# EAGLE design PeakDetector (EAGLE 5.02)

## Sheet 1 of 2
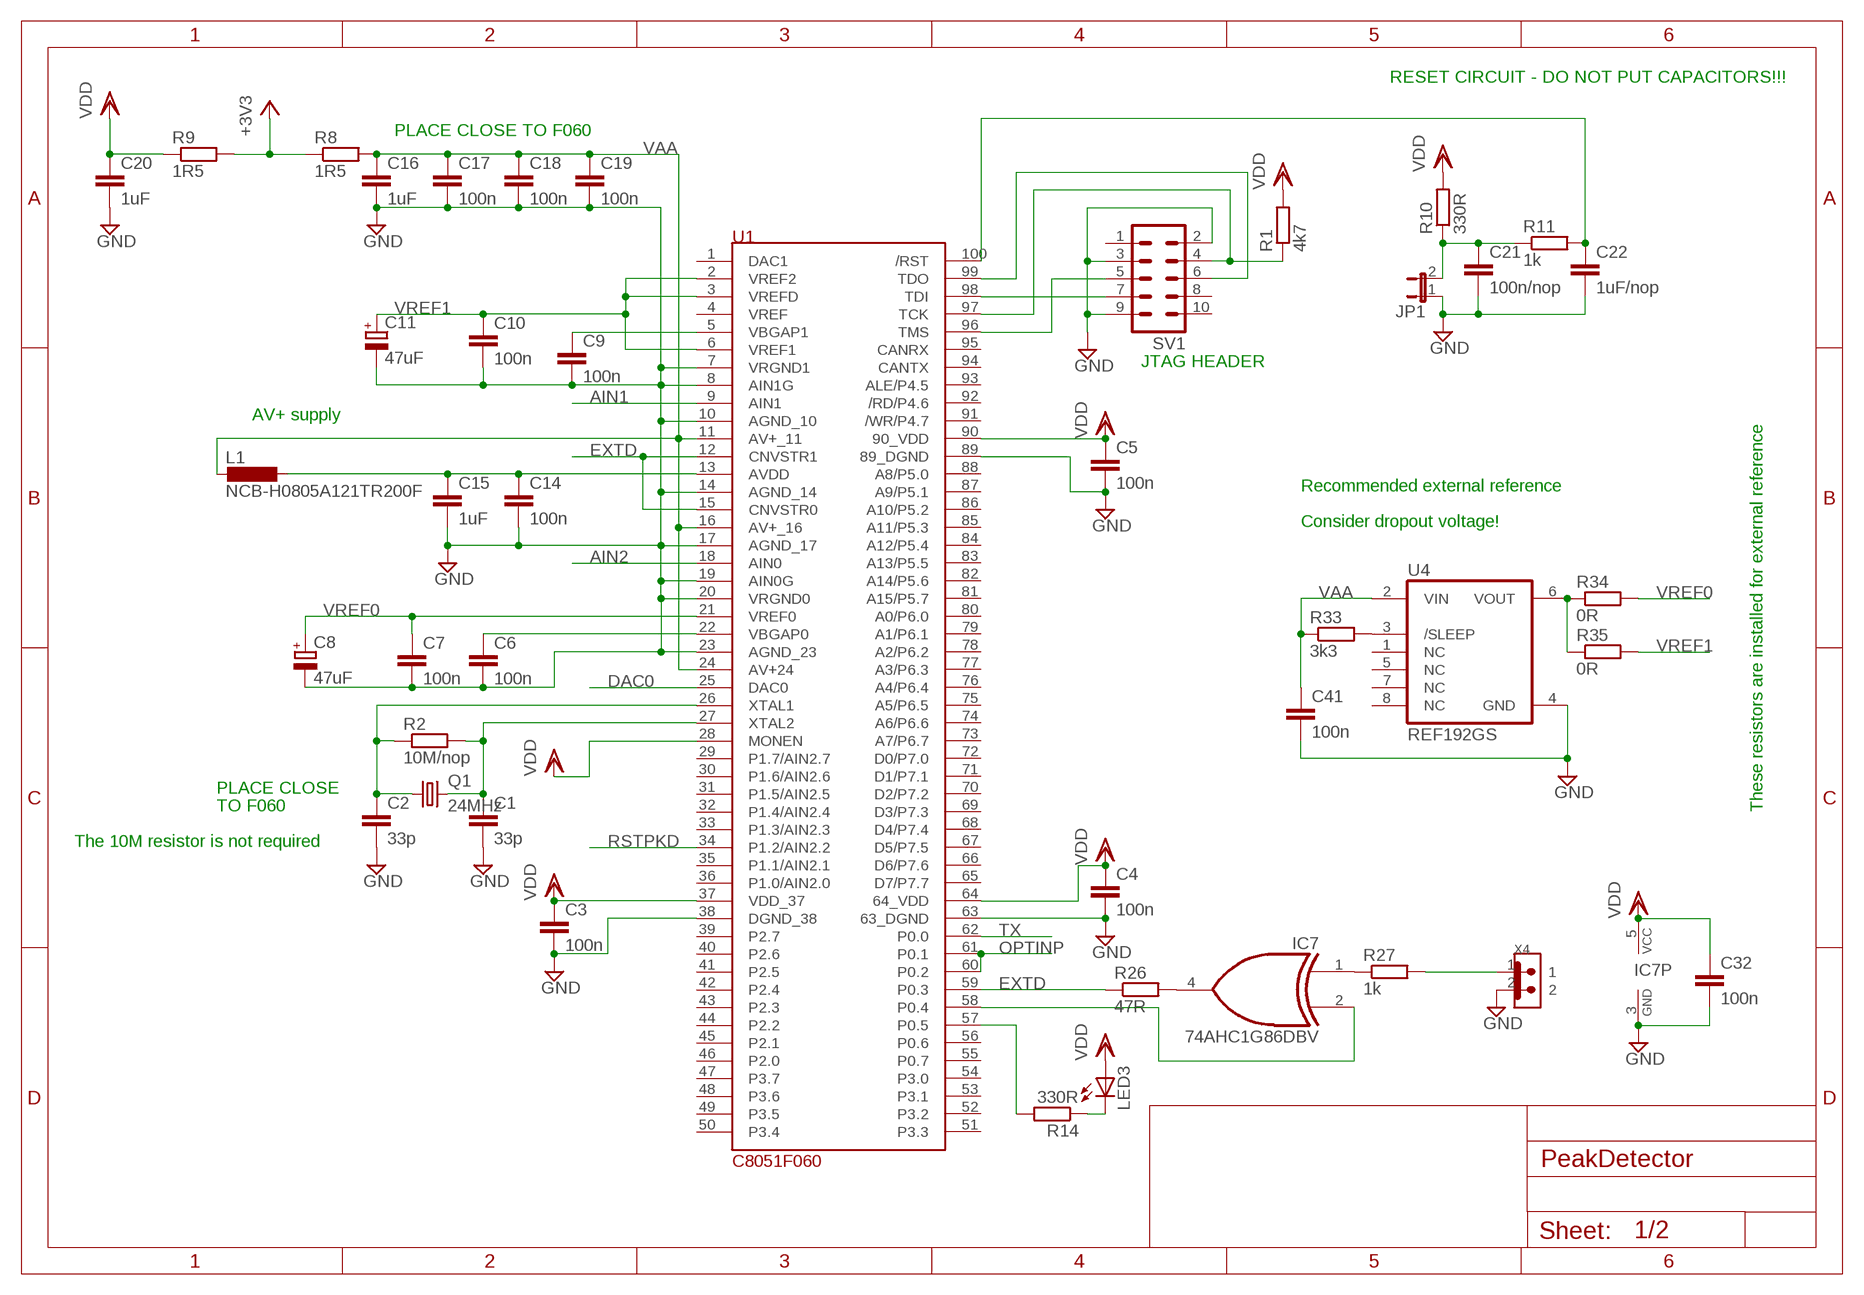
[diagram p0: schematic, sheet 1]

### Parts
C1  33p  C0805  [C0805]
C2  33p  C0805  [C0805]
C3  100n  C0805  [C0805]
C4  100n  C0805  [C0805]
C5  100n  C0805  [C0805]
C6  100n  C0805  [C0805]
C7  100n  C0805  [C0805]
C8  47uF  CPOL-EUCT6032  [CT6032]
C9  100n  C0805  [C0805]
C10  100n  C0805  [C0805]
C11  47uF  CPOL-EUCT6032  [CT6032]
C14  100n  C0805  [C0805]
C15  1uF  C0805  [C0805]
C16  1uF  C0805  [C0805]
C17  100n  C0805  [C0805]
C18  100n  C0805  [C0805]
C19  100n  C0805  [C0805]
C20  1uF  C0805  [C0805]
C21  100n/nop  C0805  [C0805]
C22  1uF/nop  C0805  [C0805]
C32  100n  C0805  [C0805]
C41  100n  C0805  [C0805]
IC7  74AHC1G86DBV  [SOT23-5]
JP1  JP1E  [JP1]
L1  NCB-H0805A121TR200F  L0805  [R0805]
LED3  LEDSMT1206  [1206]
Q1  24MHz  CRYTALHC49S  [HC49/S]
R1  4k7  R0805  [R0805]
R2  10M/nop  R0805  [R0805]
R8  1R5  R0805  [R0805]
R9  1R5  R0805  [R0805]
R10  330R  R0805  [R0805]
R11  1k  R0805  [R0805]
R14  330R  R0805  [R0805]
R26  47R  R0805  [R0805]
R27  1k  R0805  [R0805]
R33  3k3  R0805  [R0805]
R34  0R  R0805  [R0805]
R35  0R  R0805  [R0805]
SV1  ML10  [ML10]
U1  C8051F060  [TQFP100]
U4  REF192GS  [SO8]
X4  MOLEX2V  [MOLEXV2]

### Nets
+3V3: R8.1 R9.2 ; also sheet 2
AIN1: U1.9(AIN1) ; also sheet 2
AIN2: U1.18(AIN0) ; also sheet 2
DAC0: U1.25(DAC0) ; also sheet 2
EXTD: R26.1 U1.12(CNVSTR1) U1.15(CNVSTR0) U1.59(P0.3)
GND: C1.1 C2.1 C3.1 C4.1 C5.1 C6.1 C7.1 C8.- C9.1 C10.1 C11.- C14.1 C15.1 C16.1 C17.1 C18.1 C19.1 C20.1 C21.1 C22.1 C32.1 C41.1 IC7.3(GND) JP1.1 SV1.2 SV1.3 SV1.9 U1.7(VRGND1) U1.8(AIN1G) U1.10(AGND_10) U1.14(AGND_14) U1.17(AGND_17) U1.19(AIN0G) U1.20(VRGND0) U1.23(AGND_23) U1.38(DGND_38) U1.63(63_DGND) U1.89(89_DGND) U4.4(GND) X4.2 ; also sheet 2
N$1: SV1.7 U1.98(TDI)
N$2: SV1.5 U1.96(TMS)
N$3: R1.1 SV1.4 U1.97(TCK)
N$4: SV1.6 U1.99(TDO)
N$5: C1.2 Q1.2 R2.2 U1.27(XTAL2)
N$6: C2.2 Q1.1 R2.1 U1.26(XTAL1)
N$7: LED3.C R14.1
N$8: C6.2 U1.22(VBGAP0)
N$12: C9.2 U1.5(VBGAP1)
N$15: C14.2 C15.2 L1.2 U1.13(AVDD)
N$16: C21.2 JP1.2 R10.1 R11.1
N$17: C22.2 R11.2 U1.100(/RST)
N$20: R14.2 U1.57(P0.5)
N$38: IC7.4(O) R26.2
N$40: IC7.2(I1) U1.58(P0.4)
N$42: IC7.1(I0) R27.1
N$43: R27.2 X4.1
N$46: R33.2 U4.3(/SLEEP)
N$49: R34.1 R35.1 U4.6(VOUT)
OPTINP: U1.60(P0.2) U1.61(P0.1) ; also sheet 2
RSTPKD: U1.34(P1.2/AIN2.2) ; also sheet 2
TX: U1.62(P0.0) ; also sheet 2
VAA: C16.2 C17.2 C18.2 C19.2 C41.2 L1.1 R8.2 R33.1 U1.11(AV+_11) U1.16(AV+_16) U1.24(AV+24) U4.2(VIN)
VDD: C3.2 C4.2 C5.2 C20.2 C32.2 IC7.5(VCC) LED3.A R1.2 R9.1 R10.2 U1.28(MONEN) U1.37(VDD_37) U1.64(64_VDD) U1.90(90_VDD)
VREF0: C7.2 C8.+ R34.2 U1.21(VREF0)
VREF1: C10.2 C11.+ R35.2 U1.2(VREF2) U1.3(VREFD) U1.6(VREF1)
Unconnected: SV1.1 SV1.8 SV1.10 U1.1(DAC1) U1.4(VREF) U1.29(P1.7/AIN2.7) U1.30(P1.6/AIN2.6) U1.31(P1.5/AIN2.5) U1.32(P1.4/AIN2.4) U1.33(P1.3/AIN2.3) U1.35(P1.1/AIN2.1) U1.36(P1.0/AIN2.0) U1.39(P2.7) U1.40(P2.6) U1.41(P2.5) U1.42(P2.4) U1.43(P2.3) U1.44(P2.2) U1.45(P2.1) U1.46(P2.0) U1.47(P3.7) U1.48(P3.6) U1.49(P3.5) U1.50(P3.4) U1.51(P3.3) U1.52(P3.2) U1.53(P3.1) U1.54(P3.0) U1.55(P0.7) U1.56(P0.6) U1.65(D7/P7.7) U1.66(D6/P7.6) U1.67(D5/P7.5) U1.68(D4/P7.4) U1.69(D3/P7.3) U1.70(D2/P7.2) U1.71(D1/P7.1) U1.72(D0/P7.0) U1.73(A7/P6.7) U1.74(A6/P6.6) U1.75(A5/P6.5) U1.76(A4/P6.4) U1.77(A3/P6.3) U1.78(A2/P6.2) U1.79(A1/P6.1) U1.80(A0/P6.0) U1.81(A15/P5.7) U1.82(A14/P5.6) U1.83(A13/P5.5) U1.84(A12/P5.4) U1.85(A11/P5.3) U1.86(A10/P5.2) U1.87(A9/P5.1) U1.88(A8/P5.0) U1.91(/WR/P4.7) U1.92(/RD/P4.6) U1.93(ALE/P4.5) U1.94(CANTX) U1.95(CANRX) U4.1(NC) U4.5(NC) U4.7(NC) U4.8(NC)

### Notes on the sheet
- RESET CIRCUIT - DO NOT PUT CAPACITORS!!!
- PLACE CLOSE TO F060
- JTAG HEADER
- AV+ supply
- Recommended external reference
- Consider dropout voltage!
- PLACE CLOSE
- TO F060 | These resistors are installed for external reference
- The 10M resistor is not required

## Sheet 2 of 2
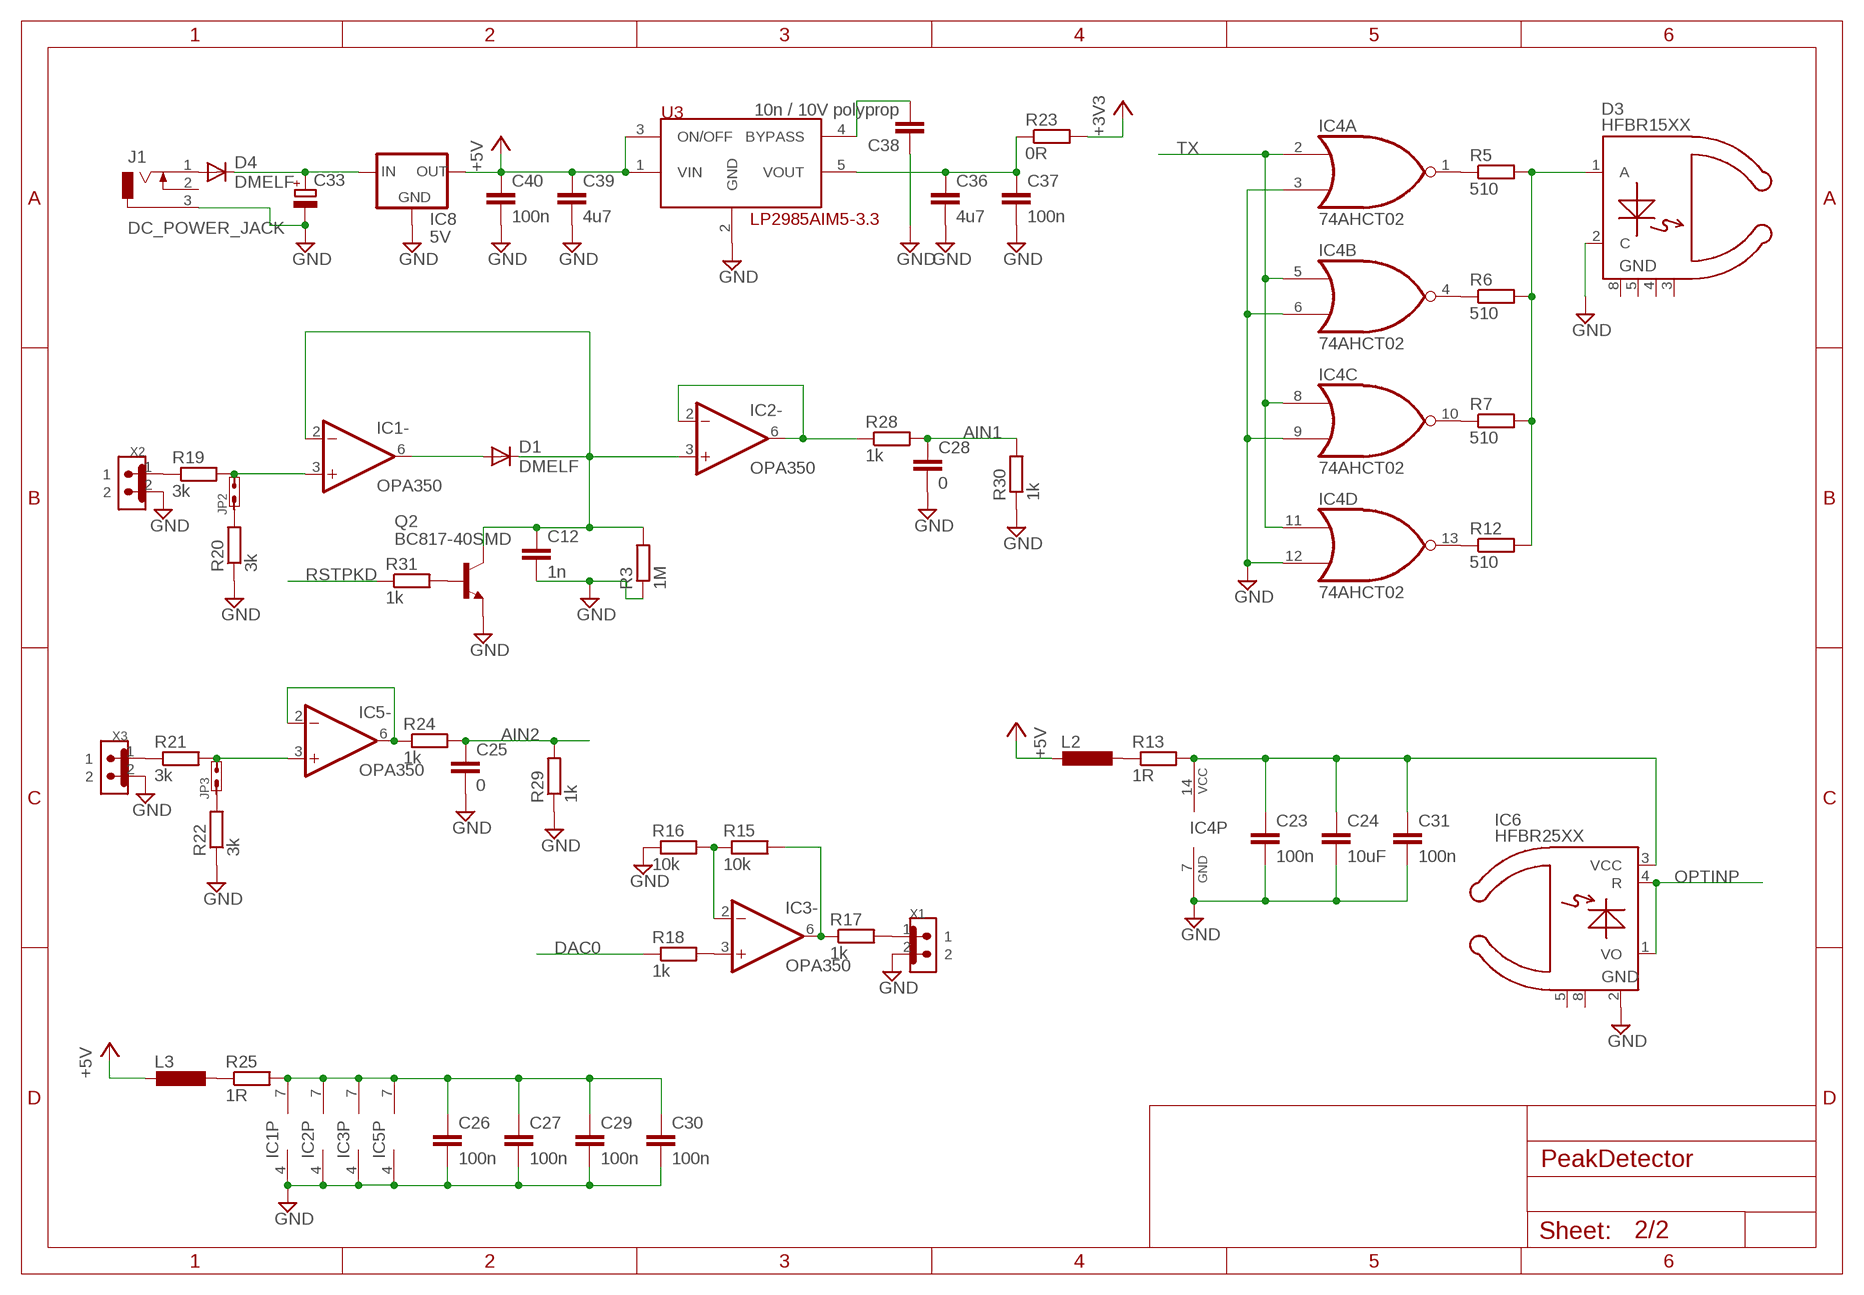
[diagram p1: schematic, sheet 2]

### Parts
C12  1n  CMKS2-5MM  [CAP200B]
C23  100n  C0805  [C0805]
C24  10uF  C0805  [C0805]
C25  0  C0805  [C0805]
C26  100n  C0805  [C0805]
C27  100n  C0805  [C0805]
C28  0  C0805  [C0805]
C29  100n  C0805  [C0805]
C30  100n  C0805  [C0805]
C31  100n  C0805  [C0805]
C33  CP  [E2,5-7]
C36  4u7  C0805  [C0805]
C37  100n  C0805  [C0805]
C38  10n / 10V polyprop  C0805  [C0805]
C39  4u7  C0805  [C0805]
C40  100n  C0805  [C0805]
D1  DMELF  [MELF-MLL41]
D3  HFBR15XX  [HFBR25XX]
D4  DMELF  [MELF-MLL41]
IC1  OPA350  OPAMPSO08  [SO08]
IC2  OPA350  OPAMPSO08  [SO08]
IC3  OPA350  OPAMPSO08  [SO08]
IC4  74AHCT02  74LS02D  [SO14]
IC5  OPA350  OPAMPSO08  [SO08]
IC6  HFBR25XX  [HFBR25XX]
IC8  5V  R-785.0-0.5  [R-78XX]
J1  DC_POWER_JACK  [DC_POWER_JACK]
JP2  JMP2  [JP2]
JP3  JMP2  [JP2]
L2  L0805  [R0805]
L3  L0805  [R0805]
Q2  BC817-40SMD  [SOT23-BEC]
R3  1M  R0805  [R0805]
R5  510  R1206  [R1206]
R6  510  R1206  [R1206]
R7  510  R1206  [R1206]
R12  510  R1206  [R1206]
R13  1R  R0805  [R0805]
R15  10k  R0805  [R0805]
R16  10k  R0805  [R0805]
R17  1k  R0805  [R0805]
R18  1k  R0805  [R0805]
R19  3k  R0805  [R0805]
R20  3k  R0805  [R0805]
R21  3k  R0805  [R0805]
R22  3k  R0805  [R0805]
R23  0R  R0805  [R0805]
R24  1k  R0805  [R0805]
R25  1R  R0805  [R0805]
R28  1k  R1206  [R1206]
R29  1k  R0805  [R0805]
R30  1k  R0805  [R0805]
R31  1k  R0805  [R0805]
U3  LP2985AIM5-3.3  LP2985  [SOT23-5L]
X1  MOLEX2V  [MOLEXV2]
X2  MOLEX2V  [MOLEXV2]
X3  MOLEX2V  [MOLEXV2]

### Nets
+3V3: R23.2 ; also sheet 1
+5V: C39.2 C40.2 IC8.OUT L2.1 L3.1 U3.1(VIN) U3.3(ON/OFF)
AIN1: C28.2 R28.2 R30.2 ; also sheet 1
AIN2: C25.2 R24.2 R29.2 ; also sheet 1
DAC0: R18.1 ; also sheet 1
GND: C12.1 C23.1 C24.1 C25.1 C26.1 C27.1 C28.1 C29.1 C30.1 C31.1 C33.- C36.1 C37.1 C38.2 C39.1 C40.1 D3.2(C) IC1.4(P:V-) IC2.4(P:V-) IC3.4(P:V-) IC4.3(A:I1) IC4.6(B:I1) IC4.7(P:GND) IC4.9(C:I1) IC4.12(D:I1) IC5.4(P:V-) IC6.2(GND) IC8.GND J1.3 Q2.E R3.1 R16.1 R20.1 R22.1 R29.1 R30.1 U3.2(GND) X1.2 X2.2 X3.2 ; also sheet 1
N$9: D1.A IC1.6(-:OUT)
N$10: C12.2 D1.C IC1.2(-:-IN) IC2.3(-:+IN) Q2.C R3.2
N$13: IC2.2(-:-IN) IC2.6(-:OUT) R28.1
N$14: C38.1 U3.4(BYPASS)
N$18: Q2.B R31.2
N$19: IC3.2(-:-IN) R15.1 R16.2
N$21: IC3.6(-:OUT) R15.2 R17.1
N$22: IC4.1(A:O) R5.1
N$23: IC4.4(B:O) R6.1
N$24: IC4.10(C:O) R7.1
N$25: IC4.13(D:O) R12.1
N$26: D3.1(A) R5.2 R6.2 R7.2 R12.2
N$27: C23.2 C24.2 C31.2 IC4.14(P:VCC) IC6.3(VCC) R13.2
N$28: IC3.3(-:+IN) R18.2
N$29: L2.2 R13.1
N$30: JP2.1 R20.2
N$31: IC1.3(-:+IN) JP2.2 R19.2
N$32: R17.2 X1.1
N$33: R19.1 X2.1
N$34: IC5.2(-:-IN) IC5.6(-:OUT) R24.1
N$35: JP3.1 R22.2
N$36: IC5.3(-:+IN) JP3.2 R21.2
N$37: R21.1 X3.1
N$39: L3.2 R25.1
N$41: C26.2 C27.2 C29.2 C30.2 IC1.7(P:V+) IC2.7(P:V+) IC3.7(P:V+) IC5.7(P:V+) R25.2
N$44: D4.A J1.1
N$45: C33.+ D4.C IC8.IN
N$47: C36.2 C37.2 R23.1 U3.5(VOUT)
OPTINP: IC6.1(VO) IC6.4(R) ; also sheet 1
RSTPKD: R31.1 ; also sheet 1
TX: IC4.2(A:I0) IC4.5(B:I0) IC4.8(C:I0) IC4.11(D:I0) ; also sheet 1
Unconnected: D3.3 D3.4 D3.5(GND) D3.8(GND) IC6.5 IC6.8 J1.2

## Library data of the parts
C1-C7 C9 C10 C14-C22 C28 C32 C36-C41 = NoiseRLC:C: Capacitor
C8 C11 = rcl:CPOL-EU: POLARIZED CAPACITOR, European symbol
C12 C23-C27 C29-C31 = Zoli:C: Capacitor
C33 = NoiseRLC:CP: Electrolytic capacitor
D1 D4 = NoiseTR:D: Diode
D3 = Zoli:HFBR15XX: OPTO TRANSMITTER
IC1-IC3 IC5 = Zoli:OPAMP: Single OP-Amp
IC4 = 74xx-us:74*02: Quad 2-input NOR gate
IC6 = Zoli:HFBR25XX: Opto receiver
IC7 = 74xx-little-us:74*1G86: 2-input EXCLUSIV-OR gate
IC8 = Zoli:R-78*: VOLTAGE REGULATOR
J1 = Zoli:DC_POWER_JACK: DC POWER JACK Source: DCJ0202.pdf
JP1 = jumper:JP1E: JUMPER
JP2 JP3 = Zoli:JMP2
L1 = NoiseRLC:L: Inductance
L2 L3 = Zoli:L: Inductance
LED3 = led:LED: LED
Q1 = crystal:CRYTAL: CRYSTAL
Q2 = transistor-npn:BC817*: NPN Transistor
R1 R2 R8-R11 R14-R18 R23 R28 R33-R35 = NoiseRLC:R: Resistor
R3 R5-R7 R12 R13 R19-R22 R24-R27 R29-R31 = Zoli:R: Resistor
SV1 = Zoli:ML10: HARTING
U1 = Zoli:C8051F060: Mixed signal microcontroller
U3 = Zoli:LP2985: Low dropout voltage regulator
U4 = Zoli:REF192: VOLATAGE REFERENCE
X1-X4 = NoiseEM:MOLEX2: 2 pin molex connector

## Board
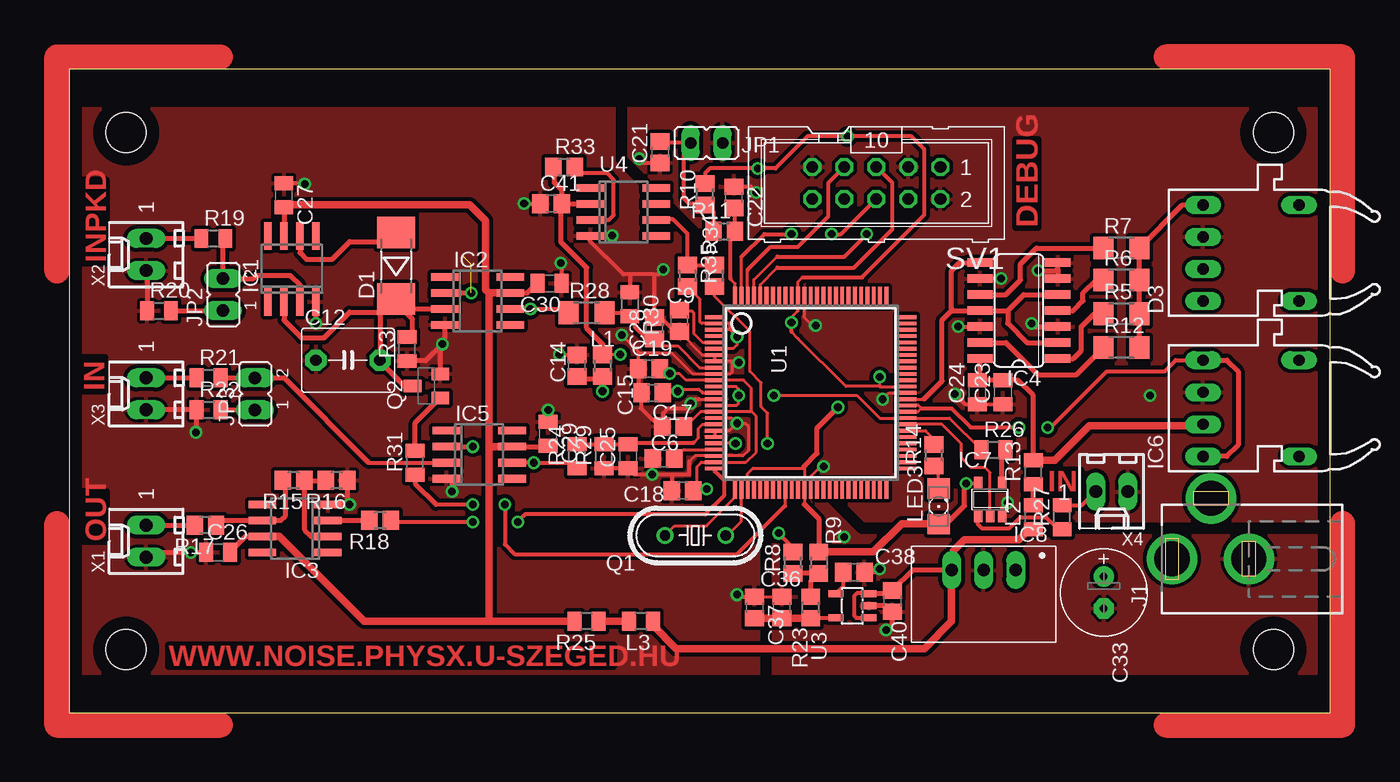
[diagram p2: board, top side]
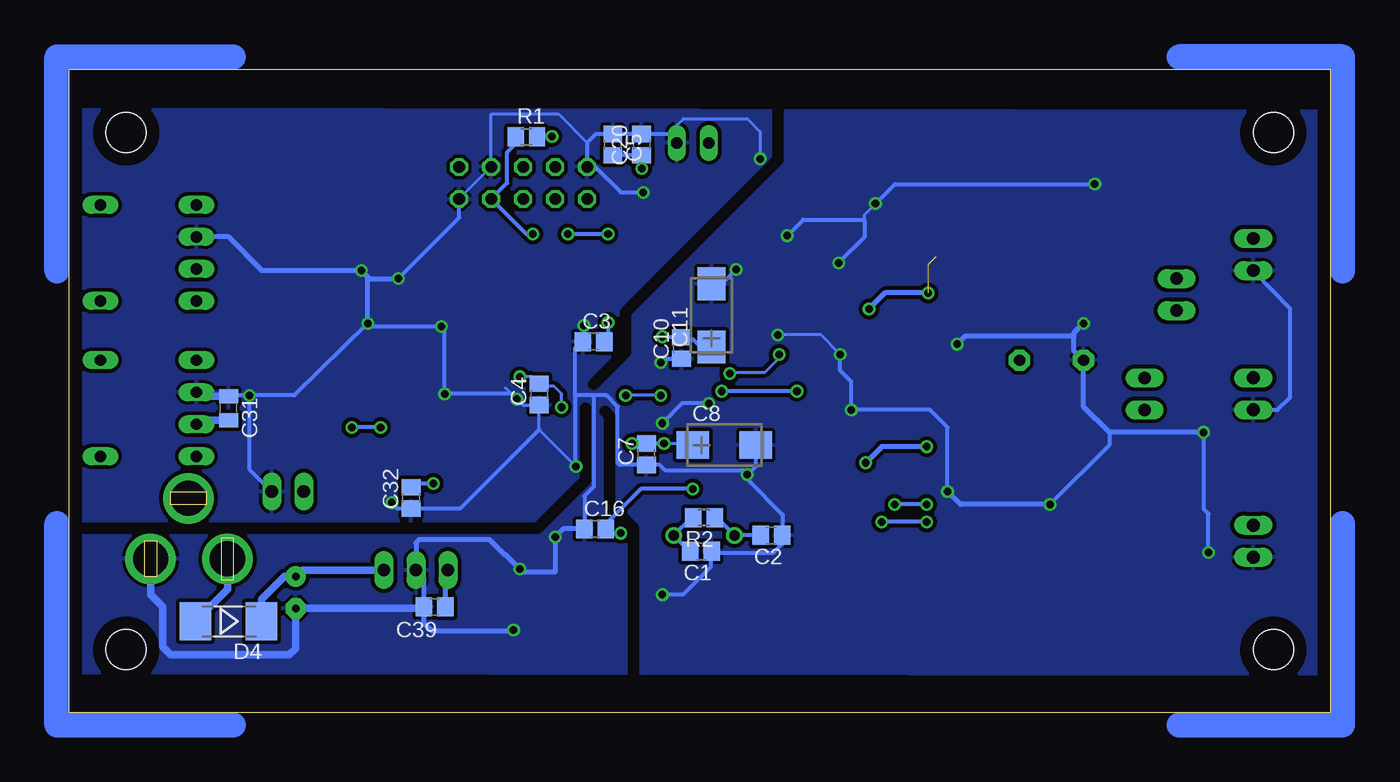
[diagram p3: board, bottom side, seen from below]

Size 100 x 51 mm. Coordinates in mm from the lower left corner, seen from the top.
Outline: 0,0 100,0 100,51 0,51 0,0
Copper layers (1*16): Top 0.035mm / dielectric 1.5mm / Bottom 0.035mm
Design rules "default": minimum track width 8mil, minimum drill 16mil, track to track 8mil, track to pad 7mil, pad to pad 7mil, via to via 8mil, smd to smd 0mil, copper to edge 40mil, drill to drill 8mil, minimum pad ring 10mil, minimum via ring 8mil, stop-mask expansion 4mil, vias tented up to drill 0mil, thermal gap 10mil
Holes 3.2 mm at 4.5,5 4.5,46 95.5,46 95.5,5
tRestrict: 10 lines
bRestrict: 11 lines

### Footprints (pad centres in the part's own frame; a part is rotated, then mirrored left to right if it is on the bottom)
C0805 = smd 1.3 x 1.5: 1 -0.85,0; 2 0.85,0
CT6032 = smd 2.6 x 2.2: + -2.5,0; - 2.5,0
CAP200B = drill 0.9 pad 1.676 octagon: 1 -2.54,0; 2 2.54,0
C0805' = smd 1.1 x 1.5: 1 -0.95,0; 2 0.95,0
E2,5-7 = drill 0.61 pad 1.6 round: + -1.27,0 | drill 0.61 pad 1.6 octagon: - 1.27,0
MELF-MLL41 = smd 2.5 x 3: A 2.625,0; C -2.625,0
HFBR25XX = drill 0.9 long: 1 0,3.81; 2 0,1.27; 3 0,-1.27; 4 0,-3.81; 5 7.62,-3.81; 8 7.62,3.81
SO08 = smd 0.6 x 2.2: 1 -1.905,-2.6; 2 -0.635,-2.6; 3 0.635,-2.6; 4 1.905,-2.6; 5 1.905,2.6; 6 0.635,2.6; 7 -0.635,2.6; 8 -1.905,2.6
SO14 = smd 0.66 x 2.032: 1 -3.81,-3.073; 2 -2.54,-3.073; 3 -1.27,-3.073; 4 0,-3.073; 5 1.27,-3.073; 6 2.54,-3.073; 7 3.81,-3.073; 8 3.81,3.073; 9 2.54,3.073; 10 1.27,3.073; 11 0,3.073; 12 -1.27,3.073; 13 -2.54,3.073; 14 -3.81,3.073
SOT23-5 = smd 0.69 x 0.99: 1 -0.95,-1.29; 2 0,-1.29; 3 0.95,-1.29; 4 0.95,1.3; 5 -0.95,1.3
R-78XX = drill 1.016 long: GND 0,-2.54; IN -2.54,-2.54; OUT 2.54,-2.54
DC_POWER_JACK = drill 2.8 pad 4 round: 1 0,3.1; 2 4.8,0; 3 0,-3
JP1 = drill 0.914 long: 1 0,-1.27; 2 0,1.27
JP2 = drill 1 long: 1 -1.27,0; 2 1.27,0
R0805 = smd 1.3 x 1.5: 1 -0.85,0; 2 0.85,0
R0805' = smd 1.1 x 1.5: 1 -0.95,0; 2 0.95,0
1206 = smd 1.6 x 1.803: A -1.422,0; C 1.422,0
HC49/S = drill 0.813 round: 1 -2.413,0; 2 2.413,0
SOT23-BEC = smd 1 x 1.4: B -0.95,-1.1; C 0,1.1; E 0.95,-1.1
R1206 = smd 1.6 x 1.803: 1 -1.422,0; 2 1.422,0
ML10 = drill 0.914 octagon: 1 -5.08,-1.27; 2 -5.08,1.27; 3 -2.54,-1.27; 4 -2.54,1.27; 5 0,-1.27; 6 0,1.27; 7 2.54,-1.27; 8 2.54,1.27; 9 5.08,-1.27; 10 5.08,1.27
TQFP100 = smd 0.3 x 1.6: 1 -6,-7.6; 2 -5.5,-7.6; 3 -5,-7.6; 4 -4.5,-7.6; 5 -4,-7.6; 6 -3.5,-7.6; 7 -3,-7.6; 8 -2.5,-7.6; 9 -2,-7.6; 10 -1.5,-7.6; 11 -1,-7.6; 12 -0.5,-7.6; 13 0,-7.6; 14 0.5,-7.6; 15 1,-7.6; 16 1.5,-7.6; 17 2,-7.6; 18 2.5,-7.6; 19 3,-7.6; 20 3.5,-7.6; 21 4,-7.6; 22 4.5,-7.6; 23 5,-7.6; 24 5.5,-7.6; 25 6,-7.6; 51 6,7.6; 52 5.5,7.6; 53 5,7.6; 54 4.5,7.6; 55 4,7.6; 56 3.5,7.6; 57 3,7.6; 58 2.5,7.6; 59 2,7.6; 60 1.5,7.6; 61 1,7.6; 62 0.5,7.6; 63 0,7.6; 64 -0.5,7.6; 65 -1,7.6; 66 -1.5,7.6; 67 -2,7.6; 68 -2.5,7.6; 69 -3,7.6; 70 -3.5,7.6; 71 -4,7.6; 72 -4.5,7.6; 73 -5,7.6; 74 -5.5,7.6; 75 -6,7.6 | smd 1.6 x 0.3: 26 7.6,-6; 27 7.6,-5.5; 28 7.6,-5; 29 7.6,-4.5; 30 7.6,-4; 31 7.6,-3.5; 32 7.6,-3; 33 7.6,-2.5; 34 7.6,-2; 35 7.6,-1.5; 36 7.6,-1; 37 7.6,-0.5; 38 7.6,0; 39 7.6,0.5; 40 7.6,1; 41 7.6,1.5; 42 7.6,2; 43 7.6,2.5; 44 7.6,3; 45 7.6,3.5; 46 7.6,4; 47 7.6,4.5; 48 7.6,5; 49 7.6,5.5; 50 7.6,6; 76 -7.6,6; 77 -7.6,5.5; 78 -7.6,5; 79 -7.6,4.5; 80 -7.6,4; 81 -7.6,3.5; 82 -7.6,3; 83 -7.6,2.5; 84 -7.6,2; 85 -7.6,1.5; 86 -7.6,1; 87 -7.6,0.5; 88 -7.6,0; 89 -7.6,-0.5; 90 -7.6,-1; 91 -7.6,-1.5; 92 -7.6,-2; 93 -7.6,-2.5; 94 -7.6,-3; 95 -7.6,-3.5; 96 -7.6,-4; 97 -7.6,-4.5; 98 -7.6,-5; 99 -7.6,-5.5; 100 -7.6,-6
SOT23-5L = smd 0.55 x 1.2: 1 -0.95,-1.3; 2 0,-1.3; 3 0.95,-1.3; 4 0.95,1.3; 5 -0.95,1.3
SO8 = smd 0.6 x 2.2: 1 -1.905,-2.6; 2 -0.635,-2.6; 3 0.635,-2.6; 4 1.905,-2.6; 5 1.905,2.6; 6 0.635,2.6; 7 -0.635,2.6; 8 -1.905,2.6
MOLEXV2 = drill 1.016 long: 1 1.27,0; 2 -1.27,0

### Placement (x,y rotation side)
C1  49.91,12.78 180 bottom
C2  44.32,14.05 180 bottom
C3  58.42,29.42 0 bottom
C4  62.74,25.23 90 bottom
C5  56.9,45.04 270 bottom
C6  47.12,20.15 0 top
C7  54.23,20.49 90 bottom
C8  48.05,21.21 0 bottom
C9  48.39,31.07 90 top
C10  51.44,28.91 90 bottom
C11  49.07,31.5 90 bottom
C12  22.1,27.94 0 top
C14  40.26,27.51 270 top
C15  46.23,25.35 0 top
C16  58.29,14.56 0 bottom
C17  47.88,22.69 0 top
C18  48.64,17.61 0 top
C19  45.97,27.26 0 top
C20  54.61,45.04 270 bottom
C21  46.86,44.43 90 top
C22  52.7,40.85 270 top
C23  100n  [C0805']  74.04,25.4 90 top
C24  10uF  [C0805']  72.01,25.4 90 top
C25  0  [C0805']  44.32,20.32 90 top
C26  100n  [C0805']  11.81,12.7 0 top
C27  100n  [C0805']  17.02,41.02 270 top
C28  46.4,30.48 270 top
C29  100n  [C0805']  37.97,22.1 270 top
C30  100n  [C0805']  38.1,34.04 180 top
C31  100n  [C0805']  87.38,24.13 270 bottom
C32  72.9,17.02 90 bottom
C33  82.04,9.53 270 top
C36  56.52,8.34 270 top
C37  54.36,8.34 270 top
C38  62.23,11.13 0 top
C39  71.04,8.38 0 bottom
C40  65.28,8.84 90 top
C41  38.21,40.35 0 top
D1  25.91,35.43 90 top
D3  89.92,36.45 0 top
D4  87.38,7.24 180 bottom
IC1  17.65,35.18 0 top
IC2  32.38,32.64 270 top
IC3  17.91,14.61 90 top
IC4  75.31,31.88 90 top
IC5  32.51,20.45 270 top
IC6  89.92,24.13 0 top
IC7  73.03,16.89 0 top
IC8  72.52,8.76 180 top
J1  90.55,12.19 90 top
JP1  50.55,45.16 90 top
JP2  12.19,33.15 90 top
JP3  14.73,25.27 90 top
L1  42.29,27.51 270 top
L2  [R0805']  76.45,15.49 90 top
L3  [R0805']  45.34,7.24 180 top
LED3  68.95,16.35 90 top
Q1  49.66,14.05 0 top
Q2  28.32,25.91 90 top
R1  63.75,45.67 0 bottom
R2  49.66,15.45 180 bottom
R3  1M  [R0805']  26.8,28.83 90 top
R5  83.44,31.62 0 top
R6  83.44,34.29 0 top
R7  83.44,36.83 0 top
R8  57.4,11.89 90 top
R9  59.44,11.89 270 top
R10  50.42,41.1 90 top
R11  51.94,38.18 0 top
R12  83.44,28.96 0 top
R13  1R  [R0805']  76.45,19.05 90 top
R14  68.58,20.4 90 top
R15  17.78,18.41 180 top
R16  21.21,18.41 180 top
R17  10.79,14.86 180 top
R18  24.64,15.24 180 top
R19  3k  [R0805']  11.43,37.59 0 top
R20  3k  [R0805']  7.11,31.88 0 top
R21  3k  [R0805']  11.05,26.54 0 top
R22  3k  [R0805']  11.05,24 0 top
R23  58.8,8.34 90 top
R24  1k  [R0805']  40.26,20.32 90 top
R25  1R  [R0805']  41.02,7.24 180 top
R26  47R  [R0805']  73.28,20.83 0 top
R27  1k  [R0805']  78.74,15.49 90 top
R28  41.02,31.7 0 top
R29  1k  [R0805']  42.42,20.32 90 top
R30  1k  [R0805']  44.45,32.38 270 top
R31  1k  [R0805']  27.43,19.81 90 top
R33  39.24,43.26 0 top
R34  51.18,34.62 270 top
R35  49.02,34.62 270 top
SV1  64.01,41.99 180 top
U1  58.8,25.35 270 top
U3  62.1,8.46 90 top
U4  43.94,39.7 270 top
X1  6.1,13.59 90 top
X2  6.1,36.32 90 top
X3  6.1,25.27 90 top
X4  82.68,17.53 180 top

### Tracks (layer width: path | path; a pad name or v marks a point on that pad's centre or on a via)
+3V3
  Top 0.406: R8.1 R9.2 58.8,10.41 R23.2
+5V
  Top 0.305: U3.1 62.42,7.51 62.23,7.7 62.23,9.22 62.48,9.48 63.37,9.48 63.4,9.45 U3.3
  Top 0.406: U3.3 65,9.41 C40.2 66.89,11.3 IC8.OUT
  Top 0.61: L3.1 46.29,6.92 48.13,5.08 67.82,5.08 69.98,7.24 IC8.OUT 70.1,11.43 70.1,12.83 70.99,13.72 75.31,13.72 76.14,14.54 L2.1
  Bottom 0.406: C39.2 70.19,11.09 IC8.OUT
AIN1
  Top 0.254: U1.9 49.99,27.35 48.26,29.08 46.95,29.08 C28.2
  Top 0.305: R28.2 44.18,31.7 R30.2 44.83,31.05 44.83,30.61 45.81,29.63 C28.2
AIN2
  Top 0.254: U1.18 50.2,22.85 49.91,22.56 49.91,21.8 49.53,21.42
  Top 0.305: 49.53,21.42 44.47,21.42 C25.2 R29.2 R24.2
DAC0  (via drill 0.6)
  Top 0.305: U1.25 51.2,19.12 51.94,18.38 51.94,17.24 50.42,15.72 50.39,15.75 36.2,15.75 v35.56,15.11 | R18.1 25.53,15.24 25.65,15.11 v32,15.11
  Bottom 0.305: v32,15.11 v35.56,15.11
EXTD  (via drill 0.6)
  Top 0.254: R26.1 69.8,23.35 U1.59 64.28,23.35 62.48,25.15 v55.88,25.15 | U1.12 52.89,25.85 53.09,25.65 v53.09,25.15 53.09,24.51 52.93,24.35 U1.15
  Bottom 0.254: v53.09,25.15 v55.88,25.15
GND  (via drill 0.6)
  Top 0.254: v64.52,24.84 65.02,25.35 U1.63 | U1.38 58.8,18.75 59.56,19.51 v59.82,19.51 | v59.18,30.69 58.93,30.69 58.3,31.31 58.3,31.33 58.29,31.34 58.3,31.34 U1.89 | 48.77,29.93 C9.1 48.55,30.22 48.39,30.18 50.21,28.35 U1.7 51.2,27.91 51.18,27.89 51.2,27.87 U1.8 52.49,27.85 52.58,27.64 52.58,27 52.43,26.85 U1.10 49.43,26.85 47.75,28.53 45.21,28.53 45.09,28.4 | U1.20 51.2,21.9 51.18,21.92 51.2,21.94 U1.19 52.37,22.35 v52.96,22.94 | 49.15,19.89 49.61,20.35 U1.23 53.42,20.35 53.85,20.78 53.85,22.69 53.59,22.94 v52.96,22.94 | v46.23,18.88 46.23,20.15 | 47.75,18.88 47.79,18.84 | 49.92,24.85 U1.14 | U1.17 52.55,23.35 v52.96,22.94 | C19.1 45.09,27.26 45.09,28.4 | U1.63 | U1.63 66.42,25.37 | 45.09,28.4 45.09,28.67 v43.81,29.94 | C36.1 56.52,9.24 56.46,9.19 C37.1 | C24.1 C23.1
  Top 0.305: v64.26,11.38 64.26,11.43 63.96,11.13 C38.2 | 49.15,19.89 49.15,18.88 47.75,18.88 v46.23,18.88 44.82,18.88 C25.1 R29.1 | 47.79,18.84 C18.1 | 52.49,27.85 52.92,27.85 v53.09,27.77 | v47.12,35.13 46.74,34.75 46.35,34.75 | 44.45,34.75 43.94,34.75 41.27,37.42 41.27,37.8 U4.4 41.29,37.8 41.27,37.81 v43.05,37.81 | 46.35,34.75 44.45,34.75 | C37.1 53.17,9.19 v52.96,9.35 | v38.86,28.4 C14.1 | v36.07,40.35 C41.1 | C22.1 54.03,41.7 v54.48,41.24 | C21.1 45.54,43.58 v45.21,43.91 | 49.92,24.85 49.62,24.85 v49.28,24.51 48.9,24.13 47.5,24.13 47.12,23.75 47.12,22.77 C17.1 46.78,22.69 45.34,24.13 45.34,25.31 C15.1 45.12,25.61 C19.1 | C9.1 48.01,30.22 46.86,31.37 46.44,31.37 C28.1 46.4,34.7 46.35,34.75 | C24.1 71.05,24.45 v70.23,25.27 | v70.48,30.61 IC4.12 | 44.45,34.75 R30.1 | C27.1 18.61,41.97 v18.67,41.91 | v37.97,24 C29.1 | C30.1 39.05,35.59 v38.99,35.66 | IC7.3 73.97,16.19 v74.42,16.64
  Top 0.406: 46.23,20.15 C6.1 | 78.38,35.18 IC4.6 | 78.38,35.18 IC4.7 | IC4.3 76.58,30.61 v76.33,30.86 | v76.83,35.05 78.26,35.05 78.38,35.18 | v73.91,34.42 IC4.9 | IC6.2 88.71,25.4 | IC3.4 v22.23,16.51 22.06,16.68 R16.1 | v30.35,17.53 30.35,18.48 IC5.4 | C26.1 v9.65,12.7 6.1,12.7 X1.2 | X3.2 R22.1 10.1,22.29 v10.03,22.23 | R20.1 6.16,34.99 X2.2 | v19.56,30.86 IC1.4 | IC2.4 29.79,29.4 v29.59,29.21 | Q2.E 29.42,29.04 v29.59,29.21 | U3.2 64.81,8.46 C40.1 65.28,7.07 v64.77,6.56 | R3.1 28.26,27.88 v29.59,29.21
  Bottom 0.254: v59.82,19.51 62.74,22.43 C4.1 62.83,24.38 62.87,24.34 64.01,24.34 64.35,24.68 v64.52,24.84 64.52,24.86 65.41,25.75 | 59.52,29.2 59.31,29.42 C3.1 59.18,29.42 v59.18,30.69 | v38.86,28.4 38.86,28.42 40.39,29.94 v43.81,29.94 | 38.86,27.13 38.85,27.13 | 36.96,39.08 36.96,39.47 v36.07,40.35 | JP1.1 51.82,46.58 51.31,47.09 46.23,47.09 45.21,46.07 v45.21,43.91 | SV1.2 69.09,40.73 66.56,43.26 SV1.3 66.55,47.47 61.21,47.47 58.93,45.18
  Bottom 0.305: 49.02,12.65 49.15,12.65 49.15,11.53 51.32,9.35 v52.96,9.35 | 49.02,12.65 44.2,12.65 43.43,13.41 43.43,14.05 | 49.02,12.65 C1.1 | 53,22.9 v52.96,22.94 51.39,24.51 v49.28,24.51 | v46.23,18.88 46.23,18.5 43.43,15.7 43.43,14.3 43.47,14.27 C2.1 | v38.86,28.4 38.86,27.13 37.97,26.24 v37.97,24 31.75,24 30.35,22.61 v30.35,17.53 | 59.78,19.47 v59.82,19.51 59.91,19.68 59.91,25.15 | v38.99,35.66 36.96,37.69 36.96,39.08 41.78,39.08 v43.05,37.81 | v54.48,41.24 56.26,41.24 58.29,43.27 58.93,43.27 | 58.93,43.27 SV1.9 | 58.93,43.27 58.93,45.18 58.22,45.89 C5.1 56.9,45.94 56.84,45.89 C20.1 52.52,45.89 51.82,45.18 JP1.1 | 47.37,35.15 v47.12,35.13 48.25,34 C11.- | C10.1 52.79,28.06 v53.09,27.77 | 64.35,24.68 64.94,25.27 v70.23,25.27 70.23,30.35 v70.48,30.61 76.07,30.61 v76.33,30.86 82.17,25.15 v85.72,25.15 | v18.67,41.91 34.51,41.91 v36.07,40.35 | 17.53,22.23 17.53,21.21 v22.23,16.51 | v10.03,22.23 10.03,16.13 9.65,15.75 v9.65,12.7 | v46.23,18.88 46.53,19.18 52.7,19.18 53.17,19.64 C7.1 56.35,19.64 56.52,19.81 56.52,24.26 57.4,25.15 58.55,25.15 | C8.- 45.55,19.55 v46.23,18.88 | X3.2 4.19,24 3.17,25.02 3.17,32 X2.2 | 59.91,25.15 59.91,28.87 59.56,29.21 59.52,29.2 | 58.55,25.15 59.91,25.15 | v85.72,25.15 87.31,25.15 C31.1 | v74.42,16.64 73.95,16.17 C32.1 69,16.17 62.74,22.43 | X4.2 85.72,19.3 v85.72,25.15 | SV1.2 69.09,39.24 v73.91,34.42 | C16.1 59.14,17.18 58.42,17.91 58.42,25.02 58.55,25.15
  Bottom 0.406: C2.1 43.43,14.05 | v76.33,30.86 76.33,34.54 | 76.33,34.54 v76.83,35.05 84.71,35.05 87.38,37.72 D3.2 | v73.91,34.42 76.2,34.42 76.33,34.54 | v22.23,16.51 29.34,16.51 v30.35,17.53 | v29.59,29.21 28.96,29.84 20.32,29.84 | 20.32,29.84 20.32,30.1 v19.56,30.86 | 20.32,29.84 20.32,28.7 C12.1 19.56,24.26 17.53,22.23 v10.03,22.23 | v64.77,6.56 64.85,6.48 71.25,6.48 71.89,7.12 71.89,7.75 C39.1 71.89,10.68 IC8.GND 72.52,13.46 72.26,13.72 66.67,13.72 65.48,12.53 65.41,12.53 v64.26,11.38 64.26,11.43 63.96,11.13 61.47,11.13 v61.47,13.92 60.83,14.56 C16.1
  Bottom 0.61: C31.1 89.6,25.08 IC6.2 | 71.89,7.75 72.4,8.26 C33.- 82.04,5.08 82.55,4.57 91.95,4.57 92.58,5.21 92.58,8.38 93.55,9.35 J1.3
  pour Top (isolate 0.305): -0.64,3.17 99.36,3.17 100,47.83 0,47.83
  pour Bottom (isolate 0.305): 0.13,3.05 100,3.17 100,47.83 0.13,47.7
N$1
  Top 0.254: U1.98 53.8,35.1 | 61.47,43.27 SV1.7
  Top 0.305: 53.8,35.1 55.63,36.92 57.78,36.92 60.2,39.34 60.2,42.01 61.47,43.27
N$2
  Top 0.254: U1.96 54.8,33.94 56.13,35.27 | 64.01,43.27 SV1.5
  Top 0.305: 56.13,35.27 62.23,35.27 65.28,38.32 65.28,42.01 64.01,43.27
N$3  (via drill 0.6)
  Top 0.254: U1.97 54.3,34.33 56.13,36.16
  Top 0.305: 56.13,36.16 61.47,36.16 v63.25,37.94
  Bottom 0.305: v63.25,37.94 63.75,37.94 66.55,40.73 | R1.1 64.6,45.09 65.28,44.42 65.28,42.01 66.55,40.73 | 66.55,40.73 SV1.4
N$4  (via drill 0.6)
  Top 0.254: U1.99 53.3,36.12 | 64.01,40.73 SV1.6
  Top 0.305: 53.3,36.12 55.12,37.94 v57.28,37.94 | v60.45,37.94 61.21,37.94 64.01,40.73
  Bottom 0.305: v57.28,37.94 v60.45,37.94
N$5
  Top 0.254: Q1.2 52.2,14.05 53.3,15.15 U1.27
  Bottom 0.305: R2.2 50.67,15.45 Q1.2 50.76,12.74 C1.2
N$6
  Top 0.254: U1.26 52.8,17.07 50.55,14.81 48.01,14.81 Q1.1
  Bottom 0.305: C2.2 Q1.1 48.64,15.45 R2.1
N$7
  Top 0.254: R14.1 68.96,19.53 68.95,19.51 LED3.C
N$8
  Top 0.254: C6.2 48.22,20.36 48.71,20.85 U1.22
N$9
  Top 0.406: IC1.6 18.29,36.45 18.8,35.94 20.83,35.94 22.23,37.34 25.27,37.34 25.27,37.85 25.91,37.85 D1.A
N$10
  Top 0.406: IC1.2 17.02,31.11 18.41,29.72 20.19,29.72 22.23,31.75 25.91,31.75 D1.C | D1.C 25.91,32.51 27.18,31.24 27.18,29.78 R3.2 | IC2.3 26.71,32 D1.C | D1.C 24.64,31.54 C12.2 24.64,27.81 26.54,25.91 Q2.C
N$12
  Top 0.254: U1.5 50.23,29.35 49.53,30.05 49.53,31.7 49.4,31.83 48.64,31.83 C9.2
N$13  (via drill 0.6)  (2 unrouted)
  Top 0.305: IC2.6 v36.58,32 39.3,32 R28.1
  Top 0.406: IC2.2 v31.88,33.27
  Bottom 0.406: v31.88,33.27 35.31,33.27 v36.58,32
N$14
  Top 0.305: U3.4 60.8,9.45 61.38,10.03 C38.1
N$15  (via drill 0.6)
  Top 0.254: v48.26,25.48 48.26,25.53 48.39,25.65 49.91,25.65 50.21,25.35 U1.13
  Top 0.305: v48.26,25.48 47.2,25.48 C15.2
  Top 0.406: C14.2 40.26,27 40.81,26.46 42.12,26.46 42.29,26.62 L1.2 42.25,26.66 42.25,25.53 42.29,25.5 v42.29,25.48
  Bottom 0.305: v42.29,25.48 v48.26,25.48
N$16
  Top 0.305: R10.1 50.42,40.35 | R11.1 51.09,39.68 50.42,40.35 | C21.2 46.84,45.28 46.61,45.31 46.75,45.16 JP1.2 49.28,45.18 48.77,44.67 48.77,40.73 49.15,40.35 50.42,40.35
N$17
  Top 0.254: U1.100 52.8,34.02 52.45,34.37
  Top 0.305: 52.45,34.37 52.45,38.31 R11.2 52.79,40.27 52.7,40.35 C22.2
N$18
  Top 0.406: R31.2 27.43,22.97 Q2.B
N$19
  Top 0.406: IC3.2 19.18,13.97 18.67,14.48 18.67,18.38 | 18.67,18.38 R15.1 | 18.67,18.38 20.32,18.38 R16.2
N$20
  Top 0.254: R14.2 68.96,21.3 67.91,22.35 U1.57
N$21
  Top 0.406: R15.2 17.14,18.33 17.14,15.62 16.76,15.24 IC3.6 12.03,15.24 R17.1
N$22
  Top 0.406: IC4.1 79.63,28.07 80.26,28.7 80.26,30.61 81.28,31.62 81.92,31.62 82.04,31.75 R5.1
N$23
  Top 0.406: IC4.4 79.63,31.88 80.39,32.64 80.39,33.27 81.41,34.29 R6.1
N$24
  Top 0.406: IC4.10 74.3,33.15 75.44,34.29 75.44,35.56 76.71,36.83 R7.1
N$25
  Top 0.406: IC4.13 74.3,29.34 76.83,26.8 79.88,26.8 82.04,28.96 R12.1
N$26
  Top 0.406: R12.2 R5.2 R6.2 R7.2 88.29,40.26 D3.1
N$27
  Top 0.406: 72.26,26.35 C24.2 | 72.26,26.35 C23.2 75.25,26.35 76.45,25.15 R13.2 | IC4.14 72.24,26.38 72.26,26.35
  Top 0.61: R13.2 78.17,20 80.9,22.73 89.79,22.73 IC6.3
  Bottom 0.61: C31.2 89.6,23.18 IC6.3
N$28
  Top 0.406: IC3.3 R18.2
N$29
  Top 0.406: L2.2 R13.1
N$30
  Top 0.406: R20.2 JP2.1
N$31
  Top 0.406: R19.2 12.19,37.4 JP2.2 14.61,34.42 14.86,34.67 17.53,34.67 18.29,33.91 IC1.3
N$32
  Top 0.406: X1.1 R17.2
N$33
  Top 0.406: X2.1 R19.1
N$34  (via drill 0.6)
  Top 0.305: IC5.6 v36.83,19.81 39.82,19.81 R24.1
  Top 0.406: IC5.2 v32,21.08
  Bottom 0.406: v32,21.08 35.56,21.08 v36.83,19.81
N$35
  Top 0.406: R22.2 JP3.1
N$36
  Top 0.305: 23.75,19.81 IC5.3
  Top 0.406: R21.2 JP3.2 17.02,26.54 23.75,19.81
N$37
  Top 0.406: X3.1 R21.1
N$38
  Top 0.406: IC7.4 73.97,20.57 R26.2
N$39
  Top 0.61: R25.1 L3.2
N$40
  Top 0.254: U1.58 69.22,22.85 70.74,21.34 70.74,20.19 71.5,19.43 72.64,19.43 73.03,19.05 IC7.2
N$41
  Top 0.406: C26.2 12.76,12.76 13.97,13.97 IC3.7 | C27.2 IC1.7 | C30.2 37.08,34.04 36.32,33.27 IC2.7 | IC5.7 37.91,21.08 C29.2
  Top 0.61: 33.27,33.27 IC2.7 | 33.27,33.27 33.02,33.53 33.02,38.99 31.75,40.26 17.21,40.26 C27.2 | 33.27,21.08 IC5.7 | 33.27,21.08 33.27,33.27 | 33.15,7.24 23.37,7.24 16.64,13.97 IC3.7 | 33.15,7.24 R25.2 | 33.27,21.08 33.27,7.37 33.15,7.24
N$42
  Top 0.305: IC7.1 72.08,14.92 72.39,14.61 74.55,14.61 75.44,15.49 77.47,15.49 78.36,14.61 R27.1
N$43
  Top 0.305: R27.2 80.33,16.45 X4.1
N$44
  Bottom 0.61: J1.1 87.45,9.79 D4.A
N$45
  Bottom 0.61: IC8.IN 81.53,11.3 C33.+ 82.93,10.79 84.75,8.97 D4.C
N$46
  Top 0.305: R33.2 40.13,43.26 40.64,42.75 42.67,42.75 43.18,42.24 43.18,39.45 42.8,39.07 U4.3
N$47
  Top 0.305: 58.8,7.46 58.8,7.45 58.87,7.51 U3.5
  Top 0.61: C37.2 56.49,7.49 56.52,7.46 C36.2 58.78,7.49 58.8,7.46 R23.1
N$49
  Top 0.305: R34.1 R35.1 49.02,37.97 47.88,39.12 46.59,39.12 U4.6
N$91
  Top 2: 12,-1 -1,-1 -1,15
N$92
  Top 2: 87,-1 101,-1 101,15
N$93
  Top 2: 12,52 -1,52 -1,35
N$94
  Top 2: 101,35 101,52 87,52
N$95
  Bottom 2: 12,-1 -1,-1 -1,15
N$96
  Bottom 2: 87,-1 101,-1 101,15
N$97
  Bottom 2: 12,52 -1,52 -1,35
N$98
  Bottom 2: 101,35 101,52 87,52
OPTINP  (via drill 0.6)
  Top 0.254: U1.61 67.34,24.35 67.56,24.13 67.29,23.85 U1.60
  Top 0.305: 67.56,24.13 69.98,24.13 71.5,22.61 v75.31,22.61 | v77.6,22.61 77.85,22.61 82.3,27.05 86.87,27.05 87.76,27.94 IC6.1
  Top 0.406: IC6.1 91.82,27.94 92.71,27.05 92.71,21.21 91.82,20.32 IC6.4
  Bottom 0.305: v75.31,22.61 v77.6,22.61
RSTPKD  (via drill 0.6)
  Top 0.254: U1.34 56.8,16.41 56.77,16.38
  Top 0.305: 56.77,16.38 52.96,12.57 35.31,12.57 34.54,13.34 v34.54,16.51 | 29.08,16.51 v32,16.51
  Top 0.406: R31.1 27.43,18.16 29.08,16.51
  Bottom 0.305: v32,16.51 v34.54,16.51
TX
  Top 0.254: U1.62 67.81,24.85
  Top 0.406: 67.81,24.85 67.81,24.89 69.22,26.29 69.22,31.11 69.98,31.88 70.1,31.88 | 70.1,31.88 IC4.11 74.42,31.88 | 74.42,31.88 75.69,33.15 IC4.5 | IC4.2 75.95,29.34 74.42,30.86 74.42,31.88 | IC4.8 70.61,35.69 69.98,35.05 69.98,32 70.1,31.88
VAA  (via drill 0.6)
  Top 0.254: C19.2 46.99,27.26 47.37,26.88 v47.62,26.88 48.39,26.88 48.91,26.35 U1.11 53.48,26.35 54.1,25.73 54.1,23.96 | C17.2 48.9,22.81 48.9,22.94 49.15,22.94 50.06,23.85 U1.16 53.95,23.85 54.1,23.96 | v43.69,28.4 43.65,28.36 L1.1 | C18.2 49.53,17.73 49.78,17.86 49.78,19.51 50.13,19.85 U1.24 53.68,19.85 54.48,20.65 54.48,23.5 54.1,23.88 54.1,23.96
  Top 0.305: 49.53,17.73 v50.55,17.73 | R8.2 57.4,13.08 v56.26,14.22
  Top 0.406: L1.1 42.29,29.21 41.02,30.48 41.02,35.27 38.99,37.31 38.99,40.35 C41.2 | C41.2 39.12,40.35 39.13,40.34 U4.2 | C41.2 39.06,41.42 38.48,42.01 38.48,43.02 38.35,43.15 38.39,43.19 R33.1
  Bottom 0.254: v47.62,26.88 47.5,27 44.83,27 43.69,28.15 v43.69,28.4
  Bottom 0.305: v50.55,17.73 54.66,17.73 57.15,15.24 57.15,14.85 C16.2 57.36,14.48 57.4,14.48 57.15,14.22 v56.26,14.22
VDD  (via drill 0.6)
  Top 0.254: U1.28 53.8,18.96 54.23,19.38 58.29,19.38 | 57.29,30.18 57.8,29.66 61.59,25.86 64.26,25.86 64.26,25.88 | v64.26,26.62 64.26,25.88 | 58.29,19.38 58.29,19.29 58.26,19.32 58.26,19.51 | 58.29,19.38 58.29,17.86 58.3,17.85 U1.37 58.3,16.64 58.29,16.51 | U1.64 64.26,25.85 64.26,25.88 | v57.28,30.94 57.28,31.34 57.8,31.86 U1.90 57.8,34.15 58.17,34.51
  Top 0.305: 57.29,30.18 v57.28,30.94 | R10.2 50.42,42.77 50.8,43.15 54.36,43.15 | 54.36,43.15 v54.61,43.15 | 54.36,43.15 56.01,43.15 58.55,45.69 v61.72,45.69 66.8,45.69 67.82,44.67 67.82,39.47 62.87,34.51 58.17,34.51 | IC7.5 71.15,18.19 v71.12,18.16
  Top 0.406: 58.26,19.51 59.31,20.56 59.31,22.56 v60.96,24.21 | LED3.A 69.54,14.93 70.99,16.38 70.99,18.03 v71.12,18.16 | 58.29,16.51 59.44,15.37 R9.1
  Top 0.61: R9.1 63.8,12.74 66.04,14.99 68.89,14.99 LED3.A
  Bottom 0.254: v64.26,26.62 63.25,26.62 62.74,26.11 C4.2 62.74,25.86 61.55,25.86 60.96,25.27 v60.96,24.21
  Bottom 0.305: C3.2 57.53,29.42 57.28,29.67 v57.28,30.94 | C5.2 56.9,44.16 56.87,44.19 C20.2 v54.61,43.15 | R1.2 62.88,45.67 62.87,45.69 v61.72,45.69 | v71.12,18.16 72.61,18.16 C32.2
VREF0  (via drill 0.6)
  Top 0.254: U1.21 52.81,21.35 v52.83,21.34 | R34.2 51.18,33.02 53.98,30.23 53.98,27.05 54.86,26.16 54.86,24.26 55.37,23.75 v55.37,21.34
  Bottom 0.254: v52.83,21.34 50.68,21.34 C8.+ | v55.37,21.34 C7.2
  Bottom 0.305: v52.83,21.34 C7.2
VREF1  (via drill 0.6)
  Top 0.254: U1.6 52.65,28.85 52.96,29.16 v52.96,29.8 52.4,30.35 | 52.4,30.35 U1.3 | 52.4,30.35 52.4,30.85 U1.2 50.17,30.85 50.04,30.99 50.04,32.76 R35.2
  Bottom 0.305: v52.96,29.8 52.92,29.76 C10.2 51.27,29.59 50.55,29.59 49.95,29 C11.+

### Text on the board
Top: DEBUG | INPKD | IN | IN | OUT | WWW.NOISE.PHYSX.U-SZEGED.HU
